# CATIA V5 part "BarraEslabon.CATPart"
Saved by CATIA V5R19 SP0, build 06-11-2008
Part number: respaldo
Material "Dull Blue": density 7860 kg/m3, Young's modulus 2e+11 Pa, Poisson ratio 0.266
Bounding box of the stored display mesh (mm): x 215.134 to 227.834, y -367.3 to 363.3, z 11158.485 to 11290.485
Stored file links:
  E:\Luis\Dropbox\3DIT\Parking\planos\cat 3 dit park8\Cadena\BarraEslabon.CATPart
  E:\Luis\Dropbox\3DIT\Parking\planos\cat 3 dit park8\Cadena\Eslabon de Cadena.........................................CATProduct
  E:\Luis\Dropbox\3DIT\Parking\planos\cat 3 dit park8\Cadena\ensamble unico eslabon.CATProduct
  E:\Luis\Dropbox\3DIT\Parking\planos\cat 3 dit park8\Cadena\Soportecuna.CATProduct
  E:\Luis\Dropbox\3DIT\Parking\planos\cat 3 dit park8\Cadena\Eslabon Bajo Completo.CATProduct
  E:\Luis\Dropbox\3DIT\Parking\planos\cat 3 dit park8\Cadena\eslabon entre uniones.CATProduct
  E:\Luis\Dropbox\3DIT\Parking\planos\cat 3 dit park8\Cadena\EslabonCompleto.CATProduct
  E:\Luis\Dropbox\3DIT\Parking\planos\cat 3 dit park8\ensamble Parking3d.CATProduct
  C:\Program Files (x86)\Dassault Systemes\B19\intel_a\startup\materials\Catalog.CATMaterial
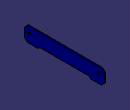
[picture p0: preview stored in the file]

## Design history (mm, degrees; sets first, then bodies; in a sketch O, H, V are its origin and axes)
Parameters
  g = 50.8
  p = 625
  b1 = 38.1
  b2 = 50.8
  d2 = 26.4
Body1 (main body), material "Dull Blue"
  DatumSurface1
  DatumCurve1 to DatumCurve18
  Sketch1 on face of DatumSurface1, origin (253.2342, 0, 0), H (0, -1, 0), V (0, 0, 1)
    line L1 (2, 11290.4854) -> (367.3, 11290.4854)
    line L2 (367.3, 11290.4854) -> (367.3, 11158.4854)
    line L3 (235.3, 11173.6854) -> (2, 11173.6854)
    point P1 (367.3, 11290.4854)
    point P2 (367.3, 11158.4854)
    line L4 (235.3, 11173.6854) -> (235.3, 11158.4854)
    line L5 (235.3, 11158.4854) -> (367.3, 11158.4854)
    line L6 (367.3, 11158.4854) -> (367.3, 11158.4854)
    point P3 (235.3, 11158.4854)
    point P4 (367.3, 11158.4854)
    construction line L7 through (120957.2298, 131880.4152) direction (-0.7071, -0.7071)
    point P5 (235.3, 11173.6854)
    construction line L8 (2, 11290.4854) -> (2, 11078.9054)
    point P6 (2, 11290.4854)
    point P8 (2, 11173.6854)
    point P9 (-363.3, 11290.4854)
    point P10 (-363.3, 11158.4854)
    point P11 (-231.3, 11158.4854)
    point P12 (-363.3, 11158.4854)
    construction line L9 (-363.3, 11290.4854) -> (-231.3, 11158.4854)
    point P13 (-231.3, 11173.6854)
    point P14 (2, 11290.4854)
    point P15 (2, 11173.6854)
    line L10 (2, 11290.4854) -> (-363.3, 11290.4854)
    line L11 (-363.3, 11290.4854) -> (-363.3, 11158.4854)
    line L12 (-231.3, 11173.6854) -> (2, 11173.6854)
    line L13 (-231.3, 11173.6854) -> (-231.3, 11158.4854)
    line L14 (-231.3, 11158.4854) -> (-363.3, 11158.4854)
    line L15 (-363.3, 11158.4854) -> (-363.3, 11158.4854)
    circle A1 centre (-310.5, 11239.6854) radius 13.2
    circle A2 centre (314.5, 11239.6854) radius 13.2
    point P16 (-310.5, 11239.6854)
    point P17 (314.5, 11239.6854)
    construction line L16 (314.5, 11239.6854) -> (-310.5, 11239.6854)
    radius A2 = 13.2 {= d2 /2/1000}
    distance A2 L2 = 39.6 {= d2 *1.5/1000}
    distance A1 L3 = 52.8 {= d2 *2/1000}
    angle L7 L5 = 45
    length L5 = 132 {= d2 *5/1000}
    length L11 = 132 {= Sketch1.length(L5)}
    distance L11 A1 = 39.6 {= d2 *1.5/1000}
    radius A1 = 13.2 {= d2/2 /1000}
    distance P16 L8 = 312.5 {= p /2/1000}
    distance P2 H = 11158.4854
    distance L11 V = 363.3
    distance P17 L8 = 312.5 (reference)
    distance P17 L1 = 50.8 {= g /1000}
    horizontal: L1 H, L3 H, L5 H, L16 H
    vertical: L2 V, L4 V, L6 V, L8 V
    coincidence: L8 P8
    symmetry: P1 P9 L8, P2 P10 L8, P3 P11 L8, P4 P12 L8, L7 L9 L8, P5 P13 L8, P6 P14 L8, P8 P15 L8, L1 L10 L8, L2 L11 L8, L3 L12 L8, L4 L13 L8, L5 L14 L8, L6 L15 L8
    concentricity: P16 A1, P17 A2
  Pad1: profile Sketch1, direction (-1, 0, 0), length 38.1, opposite side length -25.4
  DatumCurve19 to DatumCurve31
  Sketch2 on start face of Pad1, origin (227.8342, 0, 0), H (0, 1, 0), V (0, 0, 1)
    point P1 (0, 11038.4854)
    line L1 (0, 11038.4854) -> (60, 11038.4854)
    point P2 (60, 11038.4854)
    line L2 (60, 11038.4854) -> (114.9301, 11158.3304)
    point P3 (115, 11158.4829)
    line L3 (114.9301, 11158.3304) -> (114.9301, 11241.0354)
    point P4 (114.9301, 11241.0354)
    line L4 (114.9301, 11241.0354) -> (0, 11241.0354)
    point P5 (0, 11241.0354)
    construction line L5 (0, 11463.76) -> (0, 11058.4)
    point P6 (0, 11463.76)
    reference projected line E1 (-273.1, 11260.0854) -> (273.1, 11260.0854) from edge [start face of Pad1 | face of Pad1 from Sketch1.L1]
    reference projected line E2 (-593.6177, 11109.2854) -> (-745.0129, 11109.2854) from edge of DatumCurve19
    reference projected line E3 (-832.0978, 10989.2854) -> (-876.0554, 10989.2854) from edge of DatumCurve20
    reference projected line E4 (273.1, 11158.4854) -> (-273.1, 11158.4854) from edge [start face of Pad1 | face of Pad1 from Sketch1.L3]
    reference projected arc E5 centre (-1007.0978, 11084.2854) radius 25 from (-984.3712, 11094.7017) to (-1007.0978, 11109.2854) ccw from edge of DatumCurve23
    reference projected arc E6 centre (-745.0129, 11084.2854) radius 25 from (-745.0129, 11109.2854) to (-767.7395, 11094.7017) ccw from edge of DatumCurve24
    point P12 (-745.0129, 11084.2854)
    point P13 (-1007.0978, 11084.2854)
    reference projected line E7 (-767.7395, 11094.7017) -> (-809.3712, 11003.869) from edge of DatumCurve25
    reference projected line E8 (-593.6177, 11109.2854) -> (-745.0129, 11109.2854) from edge of DatumCurve26
    reference projected line E9 (-942.7395, 11003.869) -> (-984.3712, 11094.7017) from edge of DatumCurve27
    reference projected line E10 (-1007.0978, 11109.2854) -> (-1158.4931, 11109.2854) from edge of DatumCurve28
    construction line L6 (-809.3712, 11003.869) -> (-730.157, 11176.7)
    point P22 (-730.157, 11176.7)
    construction line L7 (-637.19, 11109.2854) -> (-761.0554, 11109.2854)
    point P23 (-637.19, 11109.2854)
    construction line L8 (-1092.08, 11109.2854) -> (-991.0554, 11109.2854)
    point P24 (-1092.08, 11109.2854)
    construction line L9 (-958.6054, 11038.4854) -> (-1015.2163, 11162)
    point P25 (-958.6054, 11038.4854)
    point P27 (-761.0554, 11109.2854)
    point P28 (-991.0554, 11109.2854)
    reference projected line E11 (-832.0978, 10989.2854) -> (-876.0554, 10989.2854) from edge of DatumCurve29
    construction line L10 (-1019.9583, 11172.3462) -> (-916.076, 10945.6939)
    point P29 (-1019.9583, 11172.3462)
    construction line L11 (-788.5554, 11049.2854) -> (-845.87, 10950.31)
    point P31 (-788.5554, 11049.2854)
    construction line L12 (-788.5554, 11049.2854) -> (-836.0348, 10945.6939)
    point P33 (-836.0348, 10945.6939)
    construction line L13 (-836.0348, 10945.6939) -> (-916.076, 10945.6939)
    point P34 (-836.0348, 10945.6939)
    reference projected line E12 (-832.0978, 10989.2854) -> (-876.0554, 10989.2854) from edge of DatumCurve30
    construction line L14 (-974.5584, 10989.2854) -> (-936.0554, 10989.2854)
    point P37 (-974.5584, 10989.2854)
    point P38 (-936.0554, 10989.2854)
    construction line L15 (-876.0554, 10989.2854) -> (-816.0554, 10989.2854)
    point P39 (-816.0554, 10989.2854)
    reference projected circle E13 centre (-641.0554, 11209.2854) radius 12.7 from edge of DatumCurve31
    point P40 (-641.0554, 11209.2854)
    reference projected circle E14 centre (-287.5, 11209.2854) radius 12.7 from edge [face of Pad1 from Sketch1.A2 | start face of Pad1]
    point P41 (-287.5, 11209.2854)
    point P42 (0, 11241.0354)
    point P43 (-114.9301, 11241.0354)
    line L16 (-114.9301, 11241.0354) -> (0, 11241.0354)
    line L17 (-114.9301, 11158.3304) -> (-114.9301, 11241.0354)
    point P44 (-115, 11158.4829)
    point P45 (-60, 11038.4854)
    line L18 (-60, 11038.4854) -> (-114.9301, 11158.3304)
    point P46 (0, 11038.4854)
    line L19 (0, 11038.4854) -> (-60, 11038.4854)
    point P48 (114.9301, 11158.3304)
    reference projected line E15 (-273.1, 11260.0854) -> (273.1, 11260.0854) from edge [start face of Pad1 | face of Pad1 from Sketch1.L1]
    reference projected line E16 (285.8, 11142.0854) -> (167.8, 11142.0854) from edge [start face of Pad1 | face of Pad1 from Sketch1.L14]
    distance L4 E1 = 19.05
    distance E2 E3 = 120 (reference)
    distance E4 L1 = 120
    distance P27 E11 = 120 (reference)
    distance P28 P27 = 230 (reference)
    distance P3 L5 = 115
    distance P39 P38 = 120 (reference)
    length L1 = 60
    distance P40 L7 = 100
    distance P48 E15 = 101.7549
    angle L6 L7 = 114.6236 (reference)
    angle L2 E16 = 114.624
    coincidence: P1 V, P6 V, P5 L5, P22 E7, P23 E8, P24 E10, P25 L1, P25 E9, L6 P27, L9 P28, P29 E9, P34 P33, L10 E9, P37 E12, L10 P38, L14 L15, L12 P39, P44 L18, P3 L2, P1 P46, P5 P42
    horizontal: L1 H, L4 H, L13 H, L14 H, L15 H
    vertical: L3 V, L5 V
    concentricity: P12 E6, P13 E5, P40 E13, P41 E14
    tangency: L7 E5, L8 E6, L9 E5, L10 E5, L12 E6
    midpoint: P31 E7
    symmetry: P5 P42 L5, P4 P43 L5, L4 L16 L5, L3 L17 L5, P3 P44 L5, P2 P45 L5, L2 L18 L5, P1 P46 L5, L1 L19 L5
  Pad2: profile Sketch2, direction (1, 0, 0), length 25.4, deactivated
  Sketch3 on end face of Pad2, origin (253.2342, 0, 0), H (0, 1, 0), V (0, 0, 1)
    line L1 (164.9301, 11241.0354) -> (-164.9301, 11241.0354)
    line L2 (-164.9301, 11241.0354) -> (-164.9301, 11183.8854)
    line L3 (-164.9301, 11183.8854) -> (164.9301, 11183.8854)
    line L4 (164.9301, 11183.8854) -> (164.9301, 11241.0354)
    construction line L5 (114.9301, 11241.0354) -> (0, 11241.0354)
    construction line L6 (114.9301, 11158.3304) -> (114.9301, 11241.0354)
    construction line L7 (-114.9301, 11241.0354) -> (-114.9301, 11158.3304)
    distance L1 L5 = 0
    distance L4 L6 = 50
    distance L2 L7 = 50
    horizontal: L1 H, L3 H
    vertical: L2 V, L4 V
  Pad3: profile Sketch3, direction (1, 0, 0), up to start face of Pad1, deactivated
  Chamfer1: length 26.4 {= d2 /1000}, angle 45, on edge [face of Pad1 from Sketch1.L1 | face of Pad1 from Sketch1.L2]; edge [face of Pad1 from Sketch1.L11 | face of Pad1 from Sketch1.L10]; edge [face of Pad1 from Sketch1.L2 | face of Pad1 from Sketch1.L5]; edge [face of Pad1 from Sketch1.L14 | face of Pad1 from Sketch1.L11]
  Chamfer2: length 6.6 {= d2 /4000}, angle 45, on edge [face of Pad1 from Sketch1.L5 | face of Pad1 from Sketch1.L4]; edge [face of Pad1 from Sketch1.L13 | face of Pad1 from Sketch1.L14]
  DatumSurface2
  Fillet1: radius 25, on edge [face of Pad2 from Sketch2.L19 | face of Pad2 from Sketch2.L18]; edge [face of Pad2 from Sketch2.L2 | face of Pad2 from Sketch2.L1], deactivated
  DatumSurface3
  DatumSurface4
  Sketch4 on DatumSurface4, origin (265.9342, -1.3635, 0.5939), H (0, -1, 0), V (0, 0, 1)
    reference projected curve E1 from edge [end face of Pad1 | face of Pad1 from Sketch1.A2]
    construction line L1 (298.7317, 11206.6514) -> (298.7317, 11210.7283)
    point P1 (298.7317, 11206.6514)
    point P2 (298.7317, 11210.7283)
    construction line L2 (298.876, 11209.4087) -> (298.876, 11209.4087)
    point P3 (298.876, 11209.4087)
    point P4 (298.876, 11209.4087)
    construction line L3 (298.7317, 11208.6899) -> (338.3834, 11219.4875)
    point P5 (298.7317, 11208.6899)
    point P7 (298.7317, 11208.6899)
    coincidence: P1 E1, P2 E1, P3 E1, P4 E1, P7 P5
    vertical: L1 V
    horizontal: L2 H
    midpoint: P5 L1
